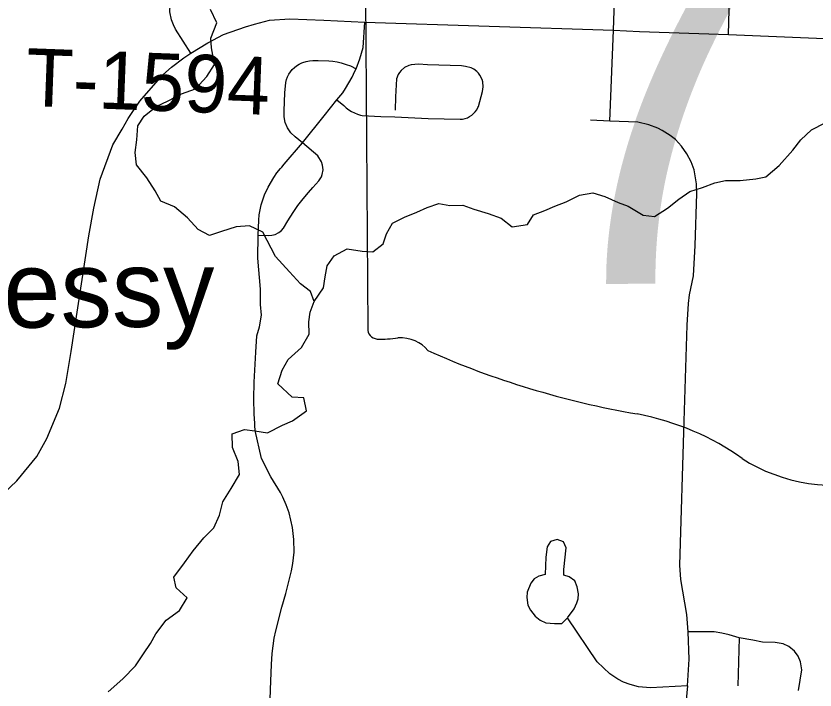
# Model space of a CAD drawing. Extents: x 114604 to 551442, y 316898 to 567001.
# Drawn here: x 175079 to 179238, y 455101 to 458606 of the extents above; entities that cross this region are included whole.
import ezdxf

# ---------------------------------------------------------------- set-up
doc = ezdxf.new("R2010")
doc.units = 0
for name, color, linetype in [('_CIVIL_CONSTRUCTION', 7, 'Continuous'), ('BD_X_Building', 7, 'Continuous'), ('GE_P_Alignment_1000_Cardinal_Points', 7, 'Continuous'), ('GE_P_Alignment_500_Curve_Data', 7, 'Continuous'), ('PM_P_Cells', 7, 'Continuous'), ('PM_P_Crosswalk', 7, 'Continuous'), ('RD_X_GR_Lt', 7, 'Continuous')]:
    doc.layers.add(name, color=color, linetype=linetype)

msp = doc.modelspace()

# ---------------------------------------------------------------- linework, layer by layer
at = {"layer": '_CIVIL_CONSTRUCTION'}
for points in [[(176320.8, 458563.2), (176398, 458584.8), (176504.7, 458591.2), (176681.9, 458584), (176895.6, 458574.3), (178188.7, 458533.3), (178323.9, 458526), (178788.3, 458509.8), (179537.2, 458478.3), (179563.2, 458477.3)], [(175988.6, 458413.4), (176078.4, 458467.3), (176159.6, 458510), (176274.5, 458550.2), (176320.8, 458563.2)], [(175631, 458018.4), (175662.9, 458073.4), (175722.9, 458163.7), (175843.7, 458300.8), (175889, 458340.1), (175952.5, 458388.8), (175988.6, 458413.4)], [(171630.2, 456788), (172131.2, 456277.9), (172246.5, 456168.6), (172422.5, 456064.3), (172620.6, 456000.6), (172816.3, 455972.8), (173018.5, 455967.5), (174218.4, 455906.5), (174360, 455900.8), (174506, 455906.3), (174622.6, 455925.2), (174808.6, 455989.4), (174980.8, 456094), (175083.5, 456189.1), (175188.2, 456315.6), (175239.1, 456408.1), (175305.4, 456565.8), (175338.2, 456694.1), (175366.2, 456860.5), (175458.4, 457463.2), (175484.3, 457607.1), (175516.9, 457757.9), (175583.1, 457935.8), (175631, 458018.4)]]:
    msp.add_lwpolyline(points, dxfattribs=at)
at = {"layer": 'GE_P_Alignment_1000_Cardinal_Points'}
for p, q in [((178788.3, 458509.8), (178810.7, 459573.5)), ((178169.7, 458059.6), (178188.7, 458533.3)), ((178842.9, 455372.6), (178836.2, 455121.9))]:
    msp.add_line(p, q, dxfattribs=at)
for points in [[(175988.6, 458413.4), (175909.7, 458537.7), (175898, 458561.2), (175888.9, 458585.7), (175879.6, 458628.8), (175887.8, 458808.9), (175888.6, 458826.9), (175887.7, 458855), (175886.9, 458871), (175885.7, 458887.7), (175882.9, 458910.8), (175880.3, 458925.5), (175878.1, 458936.4), (175875.2, 458949.9), (175872.6, 458962.1), (175868.7, 458974.3), (175865.4, 458985.4), (175861.1, 458998.3), (175857.1, 459010.1), (175850.2, 459028)], [(178188.7, 458533.3), (178199.2, 458835), (178200.7, 458867)], [(176842.7, 458318.7), (176849, 458332.1), (176869.4, 458383.1), (176885.3, 458442.1), (176895.6, 458574.3)], [(176570.3, 457947.2), (176532.9, 457978), (176510.4, 457998.8), (176492.8, 458023.9), (176480.8, 458052), (176474.9, 458082), (176474.3, 458092.4), (176475.5, 458112.5), (176477.6, 458206.4), (176483.2, 458260.8), (176487.1, 458275.4), (176492.5, 458289.6), (176499.4, 458303.1), (176507.7, 458315.8), (176517.3, 458327.6), (176528, 458338.3), (176539.9, 458347.8), (176552.6, 458356), (176566.2, 458362.8), (176572.2, 458365.3), (176589.2, 458370.2), (176606.5, 458373.5), (176624.1, 458375.2), (176641.8, 458375.4), (176651.6, 458374.8), (176706.9, 458373.1), (176728.7, 458371.1), (176750.1, 458367.7), (176771.3, 458362.6), (176798, 458353.8), (176819.6, 458346.5), (176849, 458332.1)], [(176749.4, 458169.6), (176785.9, 458140.9), (176798.1, 458129.3), (176811.3, 458118.9), (176825.6, 458109.8), (176840.5, 458102.1), (176856.2, 458095.8), (176872.4, 458091), (176880.8, 458089.2), (176978.9, 458083), (177050.3, 458082.5), (177224.5, 458073.2), (177390.3, 458069.1), (177403.7, 458070.2), (177416.5, 458072.9), (177428.7, 458077.2), (177440.4, 458083), (177452.3, 458091.1), (177461.1, 458098.6), (177469.9, 458108.1), (177477.4, 458118.7), (177483.6, 458130.2), (177485.7, 458135), (177506.5, 458212.8), (177510.8, 458238), (177508.7, 458263.5), (177505.3, 458275.9), (177494.1, 458298.9), (177486.4, 458309.2), (177477.5, 458318.4), (177462.9, 458329.5), (177448.8, 458336), (177419.1, 458344.4), (177398.7, 458346.5), (177221.5, 458353), (177174.4, 458355), (177136.7, 458352.8), (177124.6, 458349.7), (177102.1, 458338.8), (177083.1, 458322.7), (177075.3, 458312.9), (177068.8, 458302.2), (177060.1, 458278.8), (177054.3, 458185.1), (177052.5, 458115.9)], [(176462.1, 457820.5), (176474.9, 457835.1), (176570.3, 457947.2), (176683.7, 458086.9), (176749.4, 458169.6), (176779.6, 458207.5), (176794, 458229.1), (176828, 458287.5), (176842.7, 458318.7)], [(178557.7, 456498.9), (178573.4, 456998.8), (178578.9, 457111.3), (178584.3, 457156.5), (178604.9, 457254.1), (178613.4, 457412.6), (178622.6, 457682.7), (178621.9, 457732.8), (178609, 457806.6), (178594, 457848.3), (178571.7, 457890.2), (178543.8, 457928.8), (178511.1, 457963.3), (178484.9, 457985.2), (178442.7, 458011.5), (178420.3, 458022.6), (178373.8, 458040.4), (178316.4, 458053.6), (178169.7, 458059.6), (178069.3, 458064.6)], [(176338.8, 457465.7), (176394.3, 457463.9), (176411.4, 457465.5), (176427.9, 457470.2), (176448, 457480.5), (176460.4, 457490.4), (176470.6, 457502.6), (176493.4, 457540.1), (176521.5, 457585), (176546.7, 457620.7), (176573.2, 457655.4), (176600.9, 457689.1), (176623.6, 457714.9), (176655.4, 457748.6), (176668.5, 457769.9), (176673, 457781.6), (176677.3, 457806.1), (176675.3, 457831), (176670, 457848), (176651, 457879.4), (176570.3, 457947.2)], [(176327.9, 456858.1), (176332.5, 456941.9), (176347.2, 456989.4), (176357.4, 457051), (176352, 457105.3), (176351, 457185.5), (176338.1, 457346.5), (176338.8, 457465.7), (176342.2, 457544.7), (176345.3, 457572.4), (176354.8, 457623.3), (176372, 457676.2), (176390.9, 457716.5), (176420.6, 457766.6), (176437.5, 457790.4), (176455.6, 457813.2), (176462.1, 457820.5)], [(176321.9, 456487.7), (176318.3, 456535.9), (176316.7, 456614.8), (176319.2, 456701), (176327.9, 456858.1)], [(176393.4, 454783), (176404.1, 455103.9), (176409.7, 455233.5), (176412.9, 455290.2), (176423.5, 455369.9), (176431.6, 455408.1), (176463.2, 455531.5), (176483.4, 455602.3), (176513.1, 455720), (176520.6, 455759), (176526.2, 455817.6), (176525.2, 455882.9), (176518.5, 455945.8), (176500.4, 456021.8), (176486, 456062.9), (176468.5, 456102.9), (176456.2, 456127.1), (176405.6, 456210.1), (176356.3, 456305), (176324.6, 456450.2), (176322.7, 456477), (176321.9, 456487.7)], [(178574.2, 455121.5), (178582.2, 455261.4), (178577.7, 455402.6), (178571.2, 455493.2), (178539.3, 455675.8), (178534.1, 455749.1), (178557.7, 456498.9)], [(178574.2, 455121.5), (178381.3, 455111.3), (178319.9, 455116.3), (178275.3, 455128.4), (178241.5, 455141.6), (178212, 455156.7), (178170.7, 455184.5), (178103.5, 455246.6), (177950.1, 455476.1), (177984.3, 455523.4), (177998.1, 455553.5), (178004.7, 455574.8), (178006.8, 455600.6), (178000.6, 455637.5), (177988.6, 455668.1), (177959.2, 455688.9), (177930.6, 455697.2), (177931, 455726.7), (177943, 455840.4), (177929.6, 455871.2), (177896.6, 455883.3), (177862.1, 455873.8), (177844.2, 455845.9), (177836.4, 455791.9), (177833.6, 455701.8), (177799.7, 455693.2), (177776, 455679.1), (177758.5, 455655.7), (177739.5, 455608.7), (177738.9, 455580.9), (177744.1, 455541.3), (177757.4, 455516.3), (177780.8, 455485), (177808, 455463.6), (177837.3, 455449.7), (177882.1, 455445.6), (177920.1, 455446.7), (177945.8, 455472.4)], [(179152.3, 455097.2), (179169.4, 455205.7), (179162.7, 455247.8), (179149.8, 455277), (179130.6, 455302.6), (179101.5, 455326.7), (179072.8, 455340.5), (179031.1, 455348.5), (178965.6, 455350), (178914.7, 455359), (178842.9, 455372.6), (178791.4, 455387.7), (178752.3, 455396.9), (178712.7, 455402.9), (178664.6, 455403.7), (178577.7, 455402.6)], [(178574.2, 455121.5), (178560.2, 454975.6)]]:
    msp.add_lwpolyline(points, dxfattribs=at)
at = {"layer": 'GE_P_Alignment_500_Curve_Data'}
msp.add_line((176888.3, 460149.7), (176911.2, 456979.9), dxfattribs=at)
for centre, major_axis, start_param, end_param in [((176971.6, 456973.4), (61, 0.4), 3.00124, 4.508301), ((176978.5, 457297.7), (465.6, 3.4), 4.665946, 4.897461), ((177077.4, 456798.2), (167.9, 1.2), 0.519207, 1.627899), ((179176.6, 459661.5), (3998, 28.8), 4.195995, 4.488959), ((178014.1, 455563.7), (1250.9, 9), 0.823519, 1.323588), ((179358.2, 456798.9), (793.8, 5.7), 4.026481, 4.996735)]:
    msp.add_ellipse(centre, major_axis=major_axis, ratio=0.8, start_param=start_param, end_param=end_param, dxfattribs=at)
at = {"layer": 'PM_P_Cells'}
for points in [[(176631, 457121.7), (176612.7, 457173.7), (176560.4, 457213.4), (176502, 457275.1), (176429.4, 457354.7), (176364.5, 457482.5), (176294.3, 457514.1), (176224.4, 457509.6), (176148.6, 457485), (176086.8, 457464.6), (176026.6, 457496.2), (175972.2, 457556), (175903.8, 457613.6), (175833.6, 457643.2), (175803.3, 457697), (175760.8, 457764.9), (175706.3, 457832.6), (175699.8, 457896.7), (175707.3, 457962.8), (175712.7, 458035), (175746.3, 458085.3), (175807.9, 458135.8), (175871.6, 458164.3), (175941.3, 458200.9), (176013, 458227.4), (176072.4, 458291.9), (176111.9, 458354.3), (176097.3, 458440.3), (176092.9, 458490.4), (176124.3, 458570.7), (176091.7, 458640.6)], [(176517, 456624.1), (176442.5, 456693.7), (176463.9, 456763.9), (176495.5, 456820.3), (176564.9, 456882.9), (176604.4, 456951.2), (176603.9, 457015.3), (176609.5, 457065.5), (176631, 457121.7), (176680.4, 457192.2), (176688, 457250.3), (176699.6, 457306.5), (176735.1, 457358.8), (176802.8, 457395.4), (176880.8, 457383.9), (176936.8, 457380.3), (176990.4, 457420.7), (177008, 457472.9), (177039.6, 457529.2), (177101.3, 457559.7), (177165, 457586.2), (177218.8, 457610.6), (177280.6, 457631), (177336.6, 457621.4), (177404.6, 457621.9), (177462.7, 457602.2), (177536.8, 457578.7), (177604.9, 457555.1), (177661.2, 457509.4), (177741.1, 457522), (177772.7, 457572.3), (177832.4, 457594.7), (177884.2, 457617.1), (177942, 457639.6), (178011.7, 457674.1), (178081.5, 457686.6), (178143.6, 457667), (178213.8, 457635.4), (178265.9, 457617.7), (178344.2, 457570.2), (178402.2, 457562.6), (178469.8, 457607.1), (178529.4, 457653.6), (178587.1, 457694), (178652.8, 457714.5), (178716.6, 457739), (178772.5, 457751.4), (178848.4, 457749.9), (178930.3, 457758.5), (178982.2, 457768.9), (179051.7, 457829.4), (179123, 457908), (179164.5, 457962.4), (179220.1, 458014.9), (179291.7, 458051.4)], [(175559.6, 455090.8), (175635, 455159.5), (175700.4, 455226), (175741.9, 455288.4), (175779.5, 455342.8), (175807, 455393), (175860.5, 455463.5), (175930, 455514.1), (175969.5, 455580.5), (175913.1, 455632.2), (175900.7, 455688.2), (175956.1, 455762.7), (176001.6, 455825.1), (176057, 455891.6), (176108.5, 455944.1), (176138, 456010.4), (176155.5, 456078.6), (176198.9, 456149.1), (176242.3, 456221.5), (176235.8, 456289.6), (176205.2, 456361.5), (176204.7, 456433.6), (176268.5, 456456.1), (176322.5, 456448.4), (176388.5, 456438.9), (176466.1, 456477.5), (176517.9, 456499.9), (176591.5, 456552.5), (176576.9, 456620.5), (176517, 456624.1)]]:
    msp.add_lwpolyline(points, dxfattribs=at)

# ---------------------------------------------------------------- texts
at = {"layer": 'BD_X_Building'}
msp.add_text('750', height=1, rotation=0.413, dxfattribs=at).set_placement((179100.8, 458298.2))
at = {"layer": 'GE_P_Alignment_500_Curve_Data'}
msp.add_text('750', height=2088.32, rotation=0.413, dxfattribs=at).set_placement((177653.2, 457208.8))
at = {"layer": 'PM_P_Crosswalk'}
msp.add_text('T-1594', height=300, rotation=357.8427, dxfattribs=at).set_placement((175125.8, 458139.5))
at = {"layer": 'RD_X_GR_Lt'}
msp.add_text("O'Shaughnessy", height=400.009, rotation=0.4181, dxfattribs=at).set_placement((172354.3, 456964.9))

doc.saveas('drawing.dxf')
